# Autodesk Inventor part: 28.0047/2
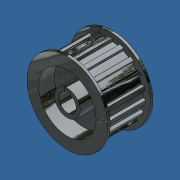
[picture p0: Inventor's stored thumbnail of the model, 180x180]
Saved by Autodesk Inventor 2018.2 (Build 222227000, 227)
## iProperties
Created: 2006-12
Document SubType Name: Modeling
Designer: Andy Moles
Material: Aluminum-6061
Part Number: 28.0047/2
Density: 2.71 g/cm^3
Description: T45 PULLEY 14mm
Stock Number: 28.0047
Appearance: Zinc
Author: Andy Moles
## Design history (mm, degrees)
sketch "Sketch1"
  geometry: L1 (-1.927, 26.982)-(-1.524, 29.17); L2 (1.927, 26.982)-(1.524, 29.17); L3 (11.073, 27.03)-(10.707, 24.842); L4 (15.084, 22.455)-(16.683, 23.977); L5 (19.077, 22.12)-(18.136, 20.071); L6 (21.534, 16.371)-(23.587, 17.23); L7 (25.254, 14.678)-(23.643, 13.144); L8 (25.717, 8.391)-(27.944, 8.508); L9 (28.652, 5.683)-(26.63, 4.755); L10 (27.049, -0.307)-(29.196, -0.889); L11 (28.945, -3.928)-(26.741, -4.085); L12 (25.484, -9.074)-(27.339, -10.286); L13 (26.084, -13.147)-(23.954, -12.569); L14 (21.157, -16.857)-(22.493, -18.635); L15 (20.429, -20.878)-(18.546, -19.693); L16 (14.537, -22.813)-(15.224, -24.929); L17 (12.543, -26.38)-(11.147, -24.648); L18 (6.342, -26.297)-(6.304, -28.522); L19 (3.298, -29.023)-(2.54, -26.931); L20 (-2.54, -26.931)-(-3.298, -29.023); L21 (-6.304, -28.522)-(-6.342, -26.297); L22 (-11.183, -24.631)-(-12.509, -26.396); L23 (-15.224, -24.929)-(-14.537, -22.813); L24 (-18.546, -19.693)-(-20.429, -20.878); L25 (-22.494, -18.635)-(-21.157, -16.856); L26 (-23.935, -12.604)-(-26.101, -13.113); L27 (-27.325, -10.322)-(-25.484, -9.074); L28 (-26.731, -4.15)-(-28.945, -3.928); L29 (-29.196, -0.89)-(-27.049, -0.307); L30 (-26.63, 4.756)-(-28.652, 5.685); L31 (-27.892, 8.674)-(-25.696, 8.455); L32 (-23.643, 13.144)-(-25.254, 14.679); L33 (-23.587, 17.23)-(-21.534, 16.371); L34 (-18.094, 20.109)-(-19.119, 22.083); L35 (-16.714, 23.955)-(-15.052, 22.477); L36 (-10.707, 24.842)-(-11.073, 27.03); L37 (-8.03, 28.085)-(-6.938, 26.146); L38 (6.938, 26.146)-(7.851, 28.135); A1 r 29.21 centre (0, 0) between (-16.714, 23.955) and (-19.119, 22.083); A2 r 27.051 centre (0, 0) between (-10.707, 24.842) and (-15.052, 22.477); A3 r 29.21 centre (0, 0) between (-8.03, 28.085) and (-11.073, 27.03); A4 r 27.051 centre (0, 0) between (-1.927, 26.982) and (-6.938, 26.146); A5 r 29.21 centre (0, 0) between (1.524, 29.17) and (-1.524, 29.17); A6 r 29.21 centre (0, 0) between (11.073, 27.03) and (7.851, 28.135); A7 r 29.21 centre (0, 0) between (19.077, 22.12) and (16.683, 23.977); A8 r 27.051 centre (0, 0) between (15.084, 22.455) and (10.707, 24.842); A9 r 27.051 centre (0, 0) between (21.534, 16.371) and (18.136, 20.071); A10 r 29.21 centre (0, 0) between (25.254, 14.678) and (23.587, 17.23); A11 r 27.051 centre (0, 0) between (25.717, 8.391) and (23.643, 13.144); A12 r 29.21 centre (0, 0) between (28.652, 5.683) and (27.944, 8.508); A13 r 27.051 centre (0, 0) between (27.049, -0.307) and (26.63, 4.755); A14 r 29.21 centre (0, 0) between (28.945, -3.928) and (29.196, -0.889); A15 r 27.051 centre (0, 0) between (25.484, -9.074) and (26.741, -4.085); A16 r 29.21 centre (0, 0) between (26.084, -13.147) and (27.339, -10.286); A17 r 27.051 centre (0, 0) between (21.157, -16.857) and (23.954, -12.569); A18 r 29.21 centre (0, 0) between (20.429, -20.878) and (22.493, -18.635); A19 r 27.051 centre (0, 0) between (14.537, -22.813) and (18.546, -19.693); A20 r 29.21 centre (0, 0) between (12.543, -26.38) and (15.224, -24.929); A21 r 27.051 centre (0, 0) between (6.342, -26.297) and (11.147, -24.648); A22 r 29.21 centre (0, 0) between (3.298, -29.023) and (6.304, -28.522); A23 r 27.051 centre (0, 0) between (-2.54, -26.931) and (2.54, -26.931); A24 r 29.21 centre (0, 0) between (-6.304, -28.522) and (-3.298, -29.023); A25 r 29.21 centre (0, 0) between (-15.224, -24.929) and (-12.509, -26.396); A26 r 29.21 centre (0, 0) between (-22.494, -18.635) and (-20.429, -20.878); A27 r 27.051 centre (0, 0) between (-11.183, -24.631) and (-6.342, -26.297); A28 r 27.051 centre (0, 0) between (-18.546, -19.693) and (-14.537, -22.813); A29 r 29.21 centre (0, 0) between (-27.325, -10.322) and (-26.101, -13.113); A30 r 27.051 centre (0, 0) between (-23.935, -12.604) and (-21.157, -16.856); A31 r 27.051 centre (0, 0) between (-26.731, -4.15) and (-25.484, -9.074); A32 r 29.21 centre (0, 0) between (-29.196, -0.89) and (-28.945, -3.928); A33 r 27.051 centre (0, 0) between (-26.63, 4.756) and (-27.049, -0.307); A34 r 29.21 centre (0, 0) between (-23.587, 17.23) and (-25.254, 14.679); A35 r 29.21 centre (0, 0) between (-27.892, 8.674) and (-28.652, 5.685); A36 r 27.051 centre (0, 0) between (-18.094, 20.109) and (-21.534, 16.371); A37 r 27.051 centre (0, 0) between (-23.643, 13.144) and (-25.696, 8.455); A38 r 27.051 centre (0, 0) between (6.938, 26.146) and (1.927, 26.982); 2 further points
  constraints: 77 point on circle, 76 end point, 38 centre point, 4 parallel, 2 coincident, 2 perpendicular
extrude "Extrusion1" new body sketch "Sketch1" stored distance "d19" = 33; taper "d20" = 0 deg
sketch "Sketch4"
  geometry: C1 r 33.02 at (0, 0); A1 r 27.051 centre (0, 0) between (6.938, 26.146) and (1.927, 26.982) reference
  constraints: 1 centre point, 1 coincident
  dimensions: "d24" = 66.04 diameter of C1
extrude "Extrusion3" join sketch "Sketch4" distance "d25" = 2; taper "d26" = 0 deg
sketch "Sketch5"
  geometry: C1 r 33.02 at (0, 0) reference; C2 r 10.5 at (0, 0); C3 r 23.5 at (0, 0)
  constraints: 2 centre point, 2 coincident
  dimensions: "d27" = 21 diameter of C2; "d28" = 47 diameter of C3
extrude "Extrusion4" cut sketch "Sketch5" distance "d29" = 12.954; taper "d30" = 0 deg
mirror "Mirror1"
sketch "Sketch6"
  geometry: L1 (-2.5, 6.538)-(-2.5, 9.3); L2 (-2.5, 9.3)-(2.5, 9.3); L3 (2.5, 9.3)-(2.5, 6.538); C1 r 10.5 at (0, 0) reference; A1 r 7 centre (0, 0) between (-2.5, 6.538) and (2.5, 6.538); 1 further point
  constraints: 6 end point, 2 point on circle, 1 centre point, 1 coincident, 1 midpoint, 1 parallel, 1 perpendicular, 1 vertical, 1 vertical alignment
  dimensions: "d31" = 14 diameter of A1 (= SHAFT_DIA); "d34" = 5 distance of L1.end L2.end (= SQUARE_KEY_SIZE); "d35" = 16.3 dimension on A1 L2 (= SHAFT_DIA + t2_KEYWAY_DEPTH)
extrude "Extrusion5" cut sketch "Sketch6" extent not by distance; stored distance "d32" = 12.954; taper "d33" = 0 deg
chamfer "Chamfer1" distance "d36" = 0.25; stored, may be unused: second distance "d37" = 2, angle "d38" = 45 deg
body "Solid1"
other parameters: "d1" = 2.159, "SHAFT_DIA" = 14 [user parameter; used in 2 equation terms], "SQUARE_KEY_SIZE" = 5 [user parameter; used in 1 equation term], "t2_KEYWAY_DEPTH" = 2.3 [user parameter; used in 1 equation term]
